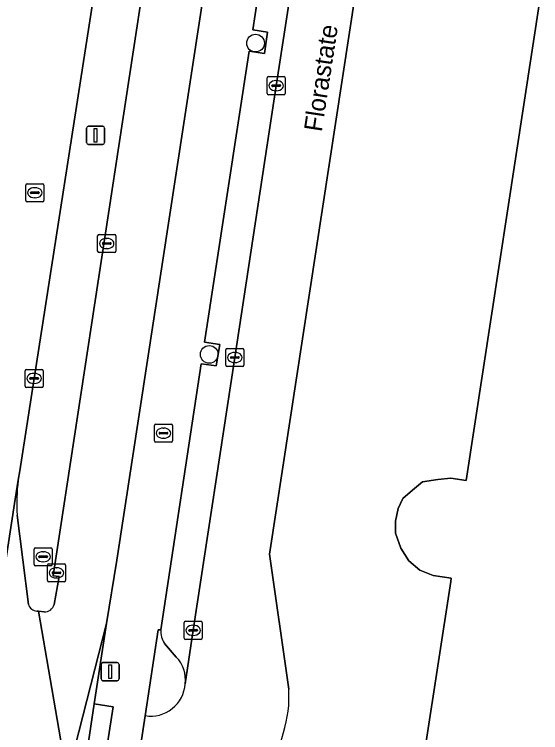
# Model space of a CAD drawing. Extents: x 161483 to 162250, y 379484 to 380833.
# Drawn here: x 161683.35 to 161712.41, y 380673.09 to 380712.77 of the extents above; entities that cross this region are included whole.
import ezdxf

# ---------------------------------------------------------------- set-up
doc = ezdxf.new("R2010")
doc.units = 0
for name, color, linetype in [('IMGEO_Berm_groen', 7, 'Continuous'), ('IMGEO_Boom', 7, 'Continuous'), ('IMGEO_Brandkraan', 7, 'Continuous'), ('IMGEO_Erf', 7, 'Continuous'), ('IMGEO_Fietspad_open', 7, 'Continuous'), ('IMGEO_Kolk', 7, 'Continuous'), ('IMGEO_Lichtmast', 7, 'Continuous'), ('IMGEO_Openbare_ruimte_label', 7, 'Continuous'), ('IMGEO_Pand', 7, 'Continuous'), ('IMGEO_Parkeervlak_open', 7, 'Continuous'), ('IMGEO_Rijbaan_lokaal_open', 7, 'Continuous'), ('IMGEO_Rijbaan_regionaal_gesloten', 7, 'Continuous'), ('IMGEO_Rioolput', 7, 'Continuous'), ('IMGEO_Verkeerseiland_open', 7, 'Continuous'), ('IMGEO_Voetpad_open', 7, 'Continuous')]:
    doc.layers.add(name, color=color, linetype=linetype)

msp = doc.modelspace()

# ---------------------------------------------------------------- linework, layer by layer
at = {"layer": 'IMGEO_Berm_groen'}
for points in [[(161696.248, 380752.176), (161698.462, 380766.661), (161699.701, 380774.77), (161696.737, 380775.208), (161696.352, 380772.576), (161695.308, 380764.889), (161694.597, 380759.447), (161693.892, 380754.498), (161693.32, 380750.34), (161692.699, 380746.151), (161690.713, 380733.056), (161689.372, 380724.138), (161687.73, 380713.853), (161684.438, 380692.656), (161683.651, 380687.555), (161683.565, 380687.03)], [(161685.545, 380680.166), (161685.819, 380681.705), (161685.484, 380681.755), (161696.248, 380752.176)], [(161683.51, 380685.102), (161684.122, 380680.157)], [(161684.591, 380679.804), (161684.689, 380679.792), (161684.986, 380679.754)]]:
    msp.add_lwpolyline(points, dxfattribs=at)
for centre, radius, start, end in [((161692.648, 380685.806), 9.165, 172.3257, 184.4063), ((161684.635, 380680.35), 0.548, 200.6286, 265.4364), ((161685.014, 380680.302), 0.548, 267.1168, 345.6659)]:
    msp.add_arc(centre, radius, start, end, dxfattribs=at)
at = {"layer": 'IMGEO_Boom'}
for centre in [(161696.666, 380711.176), (161694.109, 380693.984)]:
    msp.add_circle(centre, 0.489, dxfattribs=at)
at = {"layer": 'IMGEO_Brandkraan'}
for p, q in [((161691.081, 380689.203), (161691.081, 380690.055)), ((161691.156, 380690.129), (161692.008, 380690.129)), ((161692.082, 380690.055), (161692.082, 380689.203)), ((161691.34, 380689.623), (161691.34, 380689.635)), ((161691.383, 380689.672), (161691.781, 380689.672)), ((161691.569, 380689.909), (161691.594, 380689.909)), ((161691.824, 380689.635), (161691.824, 380689.623)), ((161691.778, 380689.586), (161691.38, 380689.586)), ((161691.592, 380689.349), (161691.567, 380689.349)), ((161692.008, 380689.129), (161691.156, 380689.129))]:
    msp.add_line(p, q, dxfattribs=at)
for points in [[(161691.081, 380689.203), (161691.081, 380690.055)], [(161691.156, 380690.129), (161692.008, 380690.129)], [(161692.082, 380690.055), (161692.082, 380689.203)], [(161692.008, 380689.129), (161691.156, 380689.129)]]:
    msp.add_lwpolyline(points, dxfattribs=at)
for centre, radius, start, end in [((161691.158, 380690.053), 0.0765, 91.552, 178.448), ((161691.158, 380690.053), 0.0765, 91.552, 178.448), ((161692.006, 380690.053), 0.0765, 1.552, 88.448), ((161692.006, 380690.053), 0.0765, 1.552, 88.448), ((161691.38, 380689.632), 0.0403, 85.8775, 175.7526), ((161691.377, 380689.622), 0.0366, 178.938, 274.7102), ((161691.781, 380689.629), 0.043, 264.8664, 352.4533), ((161691.785, 380689.634), 0.0386, 1.7309, 96.639), ((161691.158, 380689.205), 0.0765, 181.552, 268.448), ((161691.158, 380689.205), 0.0765, 181.552, 268.448), ((161692.006, 380689.205), 0.0765, 271.552, 358.448), ((161692.006, 380689.205), 0.0765, 271.552, 358.448)]:
    msp.add_arc(centre, radius, start, end, dxfattribs=at)
for centre, major_axis, ratio, start_param, end_param in [((161691.568, 380689.629), (-0.387, 0.002), 0.722429, 4.712389, 7.853982), ((161691.593, 380689.629), (-0.39, 0.002), 0.717154, 1.570796, 4.712389)]:
    msp.add_ellipse(centre, major_axis=major_axis, ratio=ratio, start_param=start_param, end_param=end_param, dxfattribs=at)
at = {"layer": 'IMGEO_Erf'}
for points in [[(161709.182, 380759.63), (161707.706, 380750), (161697.433, 380682.954), (161698.501, 380675.492)], [(161705.378, 380667.931), (161707.448, 380681.442), (161707.474, 380681.613), (161706.477, 380681.766), (161705.737, 380682.071), (161705.134, 380682.578), (161704.686, 380683.285), (161704.395, 380684.114), (161704.385, 380684.769), (161704.532, 380685.466), (161704.801, 380686.025), (161705.33, 380686.49), (161705.878, 380686.935), (161706.73, 380687.068), (161707.457, 380687.139), (161708.302, 380687.01), (161712.407, 380713.801)]]:
    msp.add_lwpolyline(points, dxfattribs=at)
for centre, radius, start, end in [((161691.938, 380675.077), 6.576, 342.3919, 3.6163), ((161691.172, 380674.728), 7.223, 265.8508, 346.8755)]:
    msp.add_arc(centre, radius, start, end, dxfattribs=at)
at = {"layer": 'IMGEO_Fietspad_open'}
for points in [[(161699.329, 380750), (161703.875, 380779.686), (161700.866, 380780.075), (161700.046, 380774.713), (161699.701, 380774.77), (161698.462, 380766.661), (161696.248, 380752.176), (161685.484, 380681.755), (161685.819, 380681.705), (161685.545, 380680.166)], [(161684.986, 380679.754), (161684.689, 380679.792), (161686.26, 380670.605), (161688.431, 380679.12), (161689.012, 380682.623), (161699.329, 380750)]]:
    msp.add_lwpolyline(points, dxfattribs=at)
msp.add_arc((161685.014, 380680.302), 0.548, 267.1168, 345.6659, dxfattribs=at)
at = {"layer": 'IMGEO_Kolk'}
for p, q in [((161697.306, 380708.4), (161697.306, 380709.252)), ((161697.381, 380709.326), (161698.233, 380709.326)), ((161697.794, 380709.106), (161697.819, 380709.106)), ((161698.307, 380709.252), (161698.307, 380708.4)), ((161697.565, 380708.82), (161697.565, 380708.832)), ((161698.003, 380708.783), (161697.605, 380708.783)), ((161697.608, 380708.869), (161698.006, 380708.869)), ((161698.049, 380708.832), (161698.049, 380708.82)), ((161698.233, 380708.326), (161697.381, 380708.326)), ((161697.817, 380708.546), (161697.792, 380708.546)), ((161687.948, 380699.681), (161687.948, 380700.533)), ((161688.023, 380700.607), (161688.875, 380700.607)), ((161688.436, 380700.387), (161688.461, 380700.387)), ((161688.949, 380700.533), (161688.949, 380699.681)), ((161688.207, 380700.101), (161688.207, 380700.113)), ((161688.645, 380700.064), (161688.247, 380700.064)), ((161688.25, 380700.15), (161688.648, 380700.15)), ((161688.691, 380700.113), (161688.691, 380700.101)), ((161688.875, 380699.607), (161688.023, 380699.607)), ((161688.459, 380699.827), (161688.434, 380699.827)), ((161695.025, 380693.382), (161695.025, 380694.234)), ((161695.1, 380694.308), (161695.952, 380694.308)), ((161695.513, 380694.088), (161695.538, 380694.088)), ((161696.026, 380694.234), (161696.026, 380693.382)), ((161695.284, 380693.802), (161695.284, 380693.814)), ((161695.722, 380693.765), (161695.324, 380693.765)), ((161695.327, 380693.851), (161695.725, 380693.851)), ((161695.768, 380693.814), (161695.768, 380693.802)), ((161695.952, 380693.308), (161695.1, 380693.308)), ((161695.536, 380693.528), (161695.511, 380693.528)), ((161683.937, 380692.23), (161683.937, 380693.082)), ((161684.012, 380693.156), (161684.864, 380693.156)), ((161684.425, 380692.936), (161684.45, 380692.936)), ((161684.938, 380693.082), (161684.938, 380692.23)), ((161684.196, 380692.65), (161684.196, 380692.662)), ((161684.634, 380692.613), (161684.236, 380692.613)), ((161684.239, 380692.699), (161684.637, 380692.699)), ((161684.68, 380692.662), (161684.68, 380692.65)), ((161684.864, 380692.156), (161684.012, 380692.156)), ((161684.448, 380692.376), (161684.423, 380692.376)), ((161685.171, 380681.488), (161685.171, 380682.34)), ((161685.246, 380682.414), (161686.098, 380682.414)), ((161685.659, 380682.194), (161685.684, 380682.194)), ((161686.172, 380682.34), (161686.172, 380681.488)), ((161685.43, 380681.908), (161685.43, 380681.92)), ((161685.868, 380681.871), (161685.47, 380681.871)), ((161685.473, 380681.957), (161685.871, 380681.957)), ((161685.914, 380681.92), (161685.914, 380681.908)), ((161686.098, 380681.414), (161685.246, 380681.414)), ((161685.682, 380681.634), (161685.657, 380681.634)), ((161692.72, 380678.313), (161692.72, 380679.165)), ((161692.795, 380679.239), (161693.647, 380679.239)), ((161693.208, 380679.019), (161693.233, 380679.019)), ((161693.721, 380679.165), (161693.721, 380678.313)), ((161692.979, 380678.733), (161692.979, 380678.745)), ((161693.417, 380678.696), (161693.019, 380678.696)), ((161693.022, 380678.782), (161693.42, 380678.782)), ((161693.463, 380678.745), (161693.463, 380678.733)), ((161693.647, 380678.239), (161692.795, 380678.239)), ((161693.231, 380678.459), (161693.206, 380678.459))]:
    msp.add_line(p, q, dxfattribs=at)
for points in [[(161697.306, 380708.4), (161697.306, 380709.252)], [(161697.381, 380709.326), (161698.233, 380709.326)], [(161698.307, 380709.252), (161698.307, 380708.4)], [(161698.233, 380708.326), (161697.381, 380708.326)], [(161687.948, 380699.681), (161687.948, 380700.533)], [(161688.023, 380700.607), (161688.875, 380700.607)], [(161688.949, 380700.533), (161688.949, 380699.681)], [(161688.875, 380699.607), (161688.023, 380699.607)], [(161695.025, 380693.382), (161695.025, 380694.234)], [(161695.1, 380694.308), (161695.952, 380694.308)], [(161696.026, 380694.234), (161696.026, 380693.382)], [(161695.952, 380693.308), (161695.1, 380693.308)], [(161683.937, 380692.23), (161683.937, 380693.082)], [(161684.012, 380693.156), (161684.864, 380693.156)], [(161684.938, 380693.082), (161684.938, 380692.23)], [(161684.864, 380692.156), (161684.012, 380692.156)], [(161685.171, 380681.488), (161685.171, 380682.34)], [(161685.246, 380682.414), (161686.098, 380682.414)], [(161686.172, 380682.34), (161686.172, 380681.488)], [(161686.098, 380681.414), (161685.246, 380681.414)], [(161692.72, 380678.313), (161692.72, 380679.165)], [(161692.795, 380679.239), (161693.647, 380679.239)], [(161693.721, 380679.165), (161693.721, 380678.313)], [(161693.647, 380678.239), (161692.795, 380678.239)]]:
    msp.add_lwpolyline(points, dxfattribs=at)
for centre, radius, start, end in [((161697.383, 380709.25), 0.0765, 91.552, 178.448), ((161697.383, 380709.25), 0.0765, 91.552, 178.448), ((161698.231, 380709.25), 0.0765, 1.552, 88.448), ((161698.231, 380709.25), 0.0765, 1.552, 88.448), ((161697.605, 380708.829), 0.0403, 85.8775, 175.7526), ((161697.602, 380708.819), 0.0366, 178.938, 274.7102), ((161698.006, 380708.826), 0.043, 264.8664, 352.4533), ((161698.01, 380708.831), 0.0386, 1.7309, 96.639), ((161697.383, 380708.402), 0.0765, 181.552, 268.448), ((161697.383, 380708.402), 0.0765, 181.552, 268.448), ((161698.231, 380708.402), 0.0765, 271.552, 358.448), ((161698.231, 380708.402), 0.0765, 271.552, 358.448), ((161688.025, 380700.531), 0.0765, 91.552, 178.448), ((161688.025, 380700.531), 0.0765, 91.552, 178.448), ((161688.873, 380700.531), 0.0765, 1.552, 88.448), ((161688.873, 380700.531), 0.0765, 1.552, 88.448), ((161688.247, 380700.11), 0.0403, 85.8775, 175.7526), ((161688.244, 380700.1), 0.0366, 178.938, 274.7102), ((161688.648, 380700.107), 0.043, 264.8664, 352.4533), ((161688.652, 380700.112), 0.0386, 1.7309, 96.639), ((161688.025, 380699.683), 0.0765, 181.552, 268.448), ((161688.025, 380699.683), 0.0765, 181.552, 268.448), ((161688.873, 380699.683), 0.0765, 271.552, 358.448), ((161688.873, 380699.683), 0.0765, 271.552, 358.448), ((161695.102, 380694.232), 0.0765, 91.552, 178.448), ((161695.102, 380694.232), 0.0765, 91.552, 178.448), ((161695.95, 380694.232), 0.0765, 1.552, 88.448), ((161695.95, 380694.232), 0.0765, 1.552, 88.448), ((161695.324, 380693.811), 0.0403, 85.8775, 175.7526), ((161695.321, 380693.801), 0.0366, 178.938, 274.7102), ((161695.725, 380693.808), 0.043, 264.8664, 352.4533), ((161695.729, 380693.813), 0.0386, 1.7309, 96.639), ((161695.102, 380693.384), 0.0765, 181.552, 268.448), ((161695.102, 380693.384), 0.0765, 181.552, 268.448), ((161695.95, 380693.384), 0.0765, 271.552, 358.448), ((161695.95, 380693.384), 0.0765, 271.552, 358.448), ((161684.014, 380693.08), 0.0765, 91.552, 178.448), ((161684.014, 380693.08), 0.0765, 91.552, 178.448), ((161684.862, 380693.08), 0.0765, 1.552, 88.448), ((161684.862, 380693.08), 0.0765, 1.552, 88.448), ((161684.236, 380692.659), 0.0403, 85.8775, 175.7526), ((161684.233, 380692.649), 0.0366, 178.938, 274.7102), ((161684.637, 380692.656), 0.043, 264.8664, 352.4533), ((161684.641, 380692.661), 0.0386, 1.7309, 96.639), ((161684.014, 380692.232), 0.0765, 181.552, 268.448), ((161684.014, 380692.232), 0.0765, 181.552, 268.448), ((161684.862, 380692.232), 0.0765, 271.552, 358.448), ((161684.862, 380692.232), 0.0765, 271.552, 358.448), ((161685.248, 380682.338), 0.0765, 91.552, 178.448), ((161685.248, 380682.338), 0.0765, 91.552, 178.448), ((161686.096, 380682.338), 0.0765, 1.552, 88.448), ((161686.096, 380682.338), 0.0765, 1.552, 88.448), ((161685.47, 380681.917), 0.0403, 85.8775, 175.7526), ((161685.467, 380681.907), 0.0366, 178.938, 274.7102), ((161685.871, 380681.914), 0.043, 264.8664, 352.4533), ((161685.875, 380681.919), 0.0386, 1.7309, 96.639), ((161685.248, 380681.49), 0.0765, 181.552, 268.448), ((161685.248, 380681.49), 0.0765, 181.552, 268.448), ((161686.096, 380681.49), 0.0765, 271.552, 358.448), ((161686.096, 380681.49), 0.0765, 271.552, 358.448), ((161692.797, 380679.163), 0.0765, 91.552, 178.448), ((161692.797, 380679.163), 0.0765, 91.552, 178.448), ((161693.645, 380679.163), 0.0765, 1.552, 88.448), ((161693.645, 380679.163), 0.0765, 1.552, 88.448), ((161693.019, 380678.742), 0.0403, 85.8775, 175.7526), ((161693.016, 380678.732), 0.0366, 178.938, 274.7102), ((161693.42, 380678.739), 0.043, 264.8664, 352.4533), ((161693.424, 380678.744), 0.0386, 1.7309, 96.639), ((161692.797, 380678.315), 0.0765, 181.552, 268.448), ((161692.797, 380678.315), 0.0765, 181.552, 268.448), ((161693.645, 380678.315), 0.0765, 271.552, 358.448), ((161693.645, 380678.315), 0.0765, 271.552, 358.448)]:
    msp.add_arc(centre, radius, start, end, dxfattribs=at)
for centre, major_axis, ratio, start_param, end_param in [((161697.793, 380708.826), (-0.387, 0.002), 0.722429, 4.712389, 7.853982), ((161697.818, 380708.826), (-0.39, 0.002), 0.717154, 1.570796, 4.712389), ((161688.435, 380700.107), (-0.387, 0.002), 0.722429, 4.712389, 7.853982), ((161688.46, 380700.107), (-0.39, 0.002), 0.717154, 1.570796, 4.712389), ((161695.512, 380693.808), (-0.387, 0.002), 0.722429, 4.712389, 7.853982), ((161695.537, 380693.808), (-0.39, 0.002), 0.717154, 1.570796, 4.712389), ((161684.424, 380692.656), (-0.387, 0.002), 0.722429, 4.712389, 7.853982), ((161684.449, 380692.656), (-0.39, 0.002), 0.717154, 1.570796, 4.712389), ((161685.658, 380681.914), (-0.387, 0.002), 0.722429, 4.712389, 7.853982), ((161685.683, 380681.914), (-0.39, 0.002), 0.717154, 1.570796, 4.712389), ((161693.207, 380678.739), (-0.387, 0.002), 0.722429, 4.712389, 7.853982), ((161693.232, 380678.739), (-0.39, 0.002), 0.717154, 1.570796, 4.712389)]:
    msp.add_ellipse(centre, major_axis=major_axis, ratio=ratio, start_param=start_param, end_param=end_param, dxfattribs=at)
at = {"layer": 'IMGEO_Lichtmast'}
for p, q in [((161687.341, 380705.68), (161687.341, 380706.48)), ((161687.341, 380706.48), (161687.341, 380705.68)), ((161687.441, 380706.58), (161688.231, 380706.58)), ((161688.231, 380706.58), (161687.441, 380706.58)), ((161688.331, 380706.48), (161688.331, 380705.68)), ((161688.331, 380705.68), (161688.331, 380706.48)), ((161688.231, 380705.58), (161687.441, 380705.58)), ((161687.441, 380705.58), (161688.231, 380705.58)), ((161688.242, 380676.957), (161689.032, 380676.957)), ((161689.032, 380676.957), (161688.242, 380676.957)), ((161688.142, 380676.057), (161688.142, 380676.857)), ((161688.142, 380676.857), (161688.142, 380676.057)), ((161689.132, 380676.857), (161689.132, 380676.057)), ((161689.132, 380676.057), (161689.132, 380676.857)), ((161689.032, 380675.957), (161688.242, 380675.957)), ((161688.242, 380675.957), (161689.032, 380675.957))]:
    msp.add_line(p, q, dxfattribs=at)
for points in [[(161687.761, 380706.455), (161687.911, 380706.455), (161687.911, 380705.705), (161687.761, 380705.705), (161687.761, 380706.455)], [(161688.562, 380676.832), (161688.712, 380676.832), (161688.712, 380676.082), (161688.562, 380676.082), (161688.562, 380676.832)]]:
    msp.add_lwpolyline(points, dxfattribs=at)
for centre, start, end in [((161687.441, 380706.48), 90, 180), ((161687.441, 380706.48), 90, 180), ((161688.231, 380706.48), 0, 90), ((161688.231, 380706.48), 360, 90), ((161687.441, 380705.68), 180, 270), ((161687.441, 380705.68), 180, 270), ((161688.231, 380705.68), 270, 0), ((161688.231, 380705.68), 270, 0), ((161688.242, 380676.857), 90, 180), ((161688.242, 380676.857), 90, 180), ((161689.032, 380676.857), 0, 90), ((161689.032, 380676.857), 360, 90), ((161688.242, 380676.057), 180, 270), ((161688.242, 380676.057), 180, 270), ((161689.032, 380676.057), 270, 0), ((161689.032, 380676.057), 270, 0)]:
    msp.add_arc(centre, 0.1, start, end, dxfattribs=at)
at = {"layer": 'IMGEO_Pand'}
msp.add_lwpolyline([(161712.407, 380713.801), (161708.302, 380687.01), (161707.457, 380687.139), (161706.73, 380687.068), (161705.878, 380686.935), (161705.33, 380686.49), (161704.801, 380686.025), (161704.532, 380685.466), (161704.385, 380684.769), (161704.395, 380684.114), (161704.686, 380683.285), (161705.134, 380682.578), (161705.737, 380682.071), (161706.477, 380681.766), (161707.474, 380681.613), (161707.448, 380681.442), (161705.378, 380667.931)], dxfattribs=at)
at = {"layer": 'IMGEO_Parkeervlak_open'}
for points in [[(161692.782, 380675.782), (161693.218, 380678.74), (161695.523, 380693.808), (161697.804, 380708.826), (161700.078, 380723.607), (161704.134, 380750), (161706.955, 380768.358), (161707.534, 380771.977)], [(161705.268, 380769.166), (161704.523, 380764.3), (161705.376, 380764.169), (161705.183, 380762.996), (161704.336, 380763.129), (161702.34, 380750), (161701.802, 380746.46), (161702.653, 380746.343), (161702.452, 380745.16), (161701.608, 380745.294), (161699.737, 380732.907), (161699.14, 380729.199), (161699.975, 380729.069), (161699.809, 380727.902), (161698.964, 380728.016), (161696.522, 380711.912), (161697.322, 380711.784), (161697.156, 380710.611), (161696.305, 380710.733), (161693.849, 380694.649), (161694.691, 380694.522), (161694.498, 380693.341), (161693.665, 380693.466), (161691.433, 380678.761)], [(161691.648, 380678.016), (161692.29, 380677.257)]]:
    msp.add_lwpolyline(points, dxfattribs=at)
for centre, radius, start, end in [((161692.534, 380678.675), 1.105, 175.554, 216.6412), ((161690.981, 380676.001), 1.814, 353.0709, 43.8223)]:
    msp.add_arc(centre, radius, start, end, dxfattribs=at)
at = {"layer": 'IMGEO_Rijbaan_lokaal_open'}
for points in [[(161707.534, 380771.977), (161706.955, 380768.358), (161704.134, 380750), (161700.078, 380723.607), (161697.804, 380708.826), (161695.523, 380693.808), (161693.218, 380678.74), (161692.782, 380675.782)], [(161698.501, 380675.492), (161697.433, 380682.954), (161707.706, 380750)], [(161683.565, 380687.03), (161683.394, 380685.989), (161680.68, 380668.409)], [(161684.122, 380680.157), (161683.51, 380685.102)], [(161684.483, 380660.221), (161684.961, 380663.244), (161685, 380663.472), (161685.747, 380668.052), (161685.811, 380668.37), (161686.26, 380670.605), (161684.689, 380679.792), (161684.591, 380679.804)], [(161690.572, 380674.025), (161689.818, 380669.085), (161689.611, 380667.675), (161690.649, 380667.524)]]:
    msp.add_lwpolyline(points, dxfattribs=at)
msp.add_lwpolyline([(161687.762, 380674.682), (161688.431, 380679.12), (161686.26, 380670.605), (161685.811, 380668.37), (161685.747, 380668.052), (161686.757, 380667.858), (161686.775, 380668.138)], close=True, dxfattribs=at)
for centre, radius, start, end in [((161692.648, 380685.806), 9.165, 172.3257, 184.4063), ((161684.635, 380680.35), 0.548, 200.6286, 265.4364), ((161690.882, 380675.903), 1.903, 260.6117, 356.3593), ((161691.938, 380675.077), 6.576, 342.3919, 3.6163), ((161691.172, 380674.728), 7.223, 265.8508, 346.8755)]:
    msp.add_arc(centre, radius, start, end, dxfattribs=at)
at = {"layer": 'IMGEO_Rijbaan_regionaal_gesloten'}
msp.add_lwpolyline([(161673.878, 380624.77), (161677.535, 380648.259), (161680.22, 380665.224), (161680.68, 380668.409), (161683.394, 380685.989), (161683.565, 380687.03), (161683.651, 380687.555), (161684.438, 380692.656), (161687.73, 380713.853), (161689.372, 380724.138), (161690.713, 380733.056), (161692.699, 380746.151), (161693.32, 380750.34), (161693.892, 380754.498)], dxfattribs=at)
msp.add_lwpolyline([(161673.878, 380624.77), (161677.535, 380648.259), (161680.22, 380665.224), (161680.68, 380668.409), (161683.394, 380685.989), (161683.565, 380687.03), (161683.651, 380687.555), (161684.438, 380692.656), (161687.73, 380713.853), (161689.372, 380724.138), (161690.713, 380733.056), (161692.699, 380746.151), (161693.32, 380750.34), (161693.892, 380754.498)], dxfattribs=at)
at = {"layer": 'IMGEO_Rioolput'}
for p, q in [((161683.98, 380702.486), (161683.98, 380703.338)), ((161684.055, 380703.412), (161684.907, 380703.412)), ((161684.468, 380703.192), (161684.493, 380703.192)), ((161684.981, 380703.338), (161684.981, 380702.486)), ((161684.239, 380702.906), (161684.239, 380702.918)), ((161684.677, 380702.869), (161684.279, 380702.869)), ((161684.282, 380702.955), (161684.68, 380702.955)), ((161684.723, 380702.918), (161684.723, 380702.906)), ((161684.907, 380702.412), (161684.055, 380702.412)), ((161684.491, 380702.632), (161684.466, 380702.632)), ((161684.513, 380683.304), (161685.365, 380683.304)), ((161684.438, 380682.378), (161684.438, 380683.23)), ((161684.926, 380683.084), (161684.951, 380683.084)), ((161685.439, 380683.23), (161685.439, 380682.378)), ((161684.697, 380682.798), (161684.697, 380682.81)), ((161685.135, 380682.761), (161684.737, 380682.761)), ((161684.74, 380682.847), (161685.138, 380682.847)), ((161684.949, 380682.524), (161684.924, 380682.524)), ((161685.181, 380682.81), (161685.181, 380682.798)), ((161685.365, 380682.304), (161684.513, 380682.304))]:
    msp.add_line(p, q, dxfattribs=at)
for points in [[(161683.98, 380702.486), (161683.98, 380703.338)], [(161684.055, 380703.412), (161684.907, 380703.412)], [(161684.981, 380703.338), (161684.981, 380702.486)], [(161684.907, 380702.412), (161684.055, 380702.412)], [(161684.513, 380683.304), (161685.365, 380683.304)], [(161684.438, 380682.378), (161684.438, 380683.23)], [(161685.439, 380683.23), (161685.439, 380682.378)], [(161685.365, 380682.304), (161684.513, 380682.304)]]:
    msp.add_lwpolyline(points, dxfattribs=at)
for centre, radius, start, end in [((161684.057, 380703.336), 0.0765, 91.552, 178.448), ((161684.057, 380703.336), 0.0765, 91.552, 178.448), ((161684.905, 380703.336), 0.0765, 1.552, 88.448), ((161684.905, 380703.336), 0.0765, 1.552, 88.448), ((161684.279, 380702.915), 0.0403, 85.8775, 175.7526), ((161684.276, 380702.905), 0.0366, 178.938, 274.7102), ((161684.68, 380702.912), 0.043, 264.8664, 352.4533), ((161684.684, 380702.917), 0.0386, 1.7309, 96.639), ((161684.057, 380702.488), 0.0765, 181.552, 268.448), ((161684.057, 380702.488), 0.0765, 181.552, 268.448), ((161684.905, 380702.488), 0.0765, 271.552, 358.448), ((161684.905, 380702.488), 0.0765, 271.552, 358.448), ((161684.515, 380683.228), 0.0765, 91.552, 178.448), ((161684.515, 380683.228), 0.0765, 91.552, 178.448), ((161685.363, 380683.228), 0.0765, 1.552, 88.448), ((161685.363, 380683.228), 0.0765, 1.552, 88.448), ((161684.737, 380682.807), 0.0403, 85.8775, 175.7526), ((161684.734, 380682.797), 0.0366, 178.938, 274.7102), ((161685.138, 380682.804), 0.043, 264.8664, 352.4533), ((161685.142, 380682.809), 0.0386, 1.7309, 96.639), ((161684.515, 380682.38), 0.0765, 181.552, 268.448), ((161684.515, 380682.38), 0.0765, 181.552, 268.448), ((161685.363, 380682.38), 0.0765, 271.552, 358.448), ((161685.363, 380682.38), 0.0765, 271.552, 358.448)]:
    msp.add_arc(centre, radius, start, end, dxfattribs=at)
for centre, major_axis, ratio, start_param, end_param in [((161684.467, 380702.912), (-0.387, 0.002), 0.722429, 4.712389, 7.853982), ((161684.492, 380702.912), (-0.39, 0.002), 0.717154, 1.570796, 4.712389), ((161684.925, 380682.804), (-0.387, 0.002), 0.722429, 4.712389, 7.853982), ((161684.95, 380682.804), (-0.39, 0.002), 0.717154, 1.570796, 4.712389)]:
    msp.add_ellipse(centre, major_axis=major_axis, ratio=ratio, start_param=start_param, end_param=end_param, dxfattribs=at)
at = {"layer": 'IMGEO_Verkeerseiland_open'}
for points in [[(161691.433, 380678.761), (161691.296, 380678.761), (161690.572, 380674.025)], [(161692.29, 380677.257), (161691.648, 380678.016)]]:
    msp.add_lwpolyline(points, dxfattribs=at)
for centre, radius, start, end in [((161692.534, 380678.675), 1.105, 175.554, 216.6412), ((161690.981, 380676.001), 1.814, 353.0709, 43.8223), ((161690.882, 380675.903), 1.903, 260.6117, 356.3593)]:
    msp.add_arc(centre, radius, start, end, dxfattribs=at)
at = {"layer": 'IMGEO_Voetpad_open'}
for points in [[(161709.533, 380819.684), (161709.319, 380818.367), (161708.16, 380811.246), (161706.37, 380799.426), (161704.73, 380788.463), (161704.217, 380785.06), (161704.125, 380783.519), (161704.009, 380780.896), (161703.875, 380779.686), (161699.329, 380750), (161689.012, 380682.623), (161688.431, 380679.12), (161687.762, 380674.682), (161688.805, 380674.508), (161687.739, 380667.669), (161686.757, 380667.858)], [(161688.303, 380665.811), (161689.316, 380665.661), (161689.325, 380665.721), (161689.611, 380667.675), (161689.818, 380669.085), (161690.572, 380674.025), (161691.296, 380678.761), (161691.433, 380678.761), (161693.665, 380693.466), (161694.498, 380693.341), (161694.691, 380694.522), (161693.849, 380694.649), (161696.305, 380710.733), (161697.156, 380710.611), (161697.322, 380711.784), (161696.522, 380711.912), (161698.964, 380728.016), (161699.809, 380727.902), (161699.975, 380729.069), (161699.14, 380729.199), (161699.737, 380732.907), (161701.608, 380745.294)]]:
    msp.add_lwpolyline(points, dxfattribs=at)
msp.add_lwpolyline([(161688.805, 380674.508), (161687.762, 380674.682), (161686.775, 380668.138), (161686.757, 380667.858), (161687.739, 380667.669)], close=True, dxfattribs=at)

# ---------------------------------------------------------------- texts
at = {"layer": 'IMGEO_Openbare_ruimte_label'}
msp.add_text('Florastate', height=1, rotation=81.3105, dxfattribs=at).set_placement((161700.321, 380706.241))

doc.saveas('drawing.dxf')
